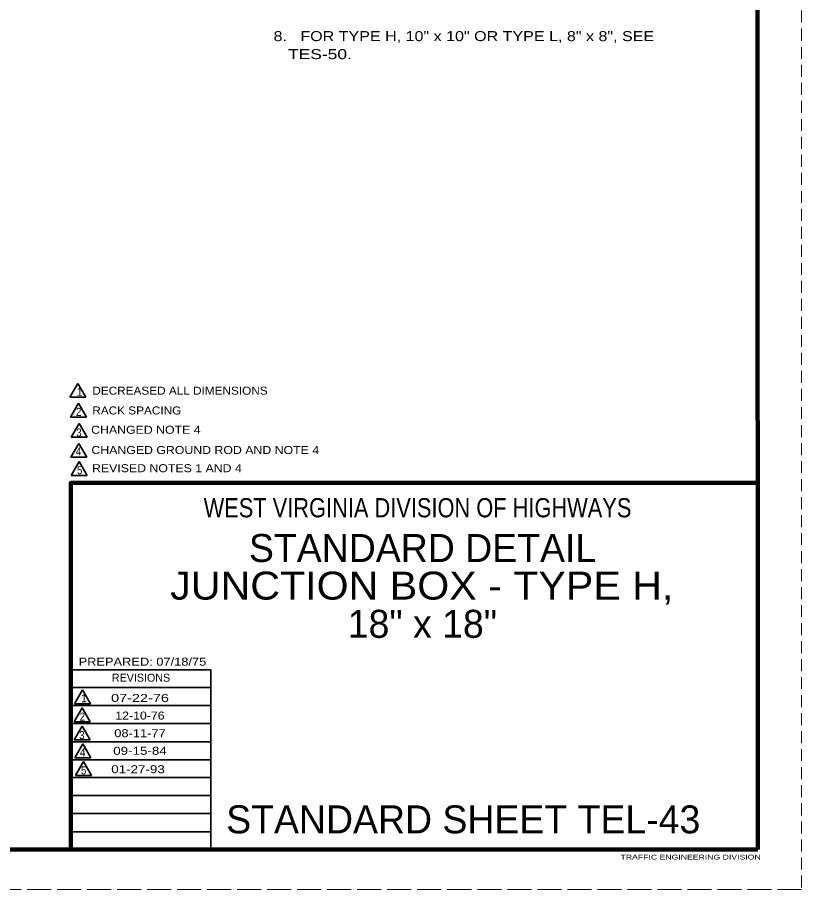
# Model space of a CAD drawing. Extents: x 788 to 1469, y -1 to 439.
# Drawn here: x 1272.6 to 1468.5, y -1 to 216.9 of the extents above; entities that cross this region are included whole.
import ezdxf
from ezdxf.enums import TextEntityAlignment as Align

# ---------------------------------------------------------------- set-up
doc = ezdxf.new("R2010")
doc.units = 0
doc.linetypes.add('LONG_DASHED', pattern=[7.5, 6, -1.5])
doc.linetypes.add('MEDIUM_DASHED', pattern=[4.5, 3, -1.5])
doc.layers.add('1', color=7, linetype='Continuous', lineweight=35)
doc.layers.add('61', color=7, linetype='Continuous', lineweight=35)

msp = doc.modelspace()

# ---------------------------------------------------------------- linework, layer by layer
at = {"layer": '1', "linetype": 'MEDIUM_DASHED', "lineweight": 13}
msp.add_line((1468.547, 439.076), (1468.527, -0.944), dxfattribs=at)
at = {"layer": '1'}
for p, q in [((1287.672, 125.464), (1285.672, 122)), ((1287.672, 125.464), (1289.672, 122)), ((1289.672, 122), (1285.672, 122)), ((1287.897, 120.518), (1285.897, 117.054)), ((1287.897, 120.518), (1289.897, 117.054)), ((1289.897, 117.054), (1285.897, 117.054)), ((1287.989, 115.479), (1285.989, 112.015)), ((1287.989, 115.479), (1289.989, 112.015)), ((1289.989, 112.015), (1285.989, 112.015)), ((1287.91, 110.492), (1285.91, 107.028)), ((1287.91, 110.492), (1289.91, 107.028)), ((1289.91, 107.028), (1285.91, 107.028)), ((1288.063, 105.955), (1286.063, 102.491)), ((1288.063, 105.955), (1290.063, 102.491)), ((1290.063, 102.491), (1286.063, 102.491)), ((1320.927, 49.476), (1285.947, 49.476)), ((1288.881, 48.884), (1286.881, 45.42)), ((1288.881, 48.884), (1290.881, 45.42)), ((1320.927, 44.976), (1285.947, 44.976)), ((1288.805, 44.425), (1286.805, 40.96)), ((1290.881, 45.42), (1286.881, 45.42)), ((1288.805, 44.425), (1290.805, 40.96)), ((1320.927, 40.476), (1285.947, 40.476)), ((1288.804, 39.889), (1286.804, 36.425)), ((1290.805, 40.96), (1286.805, 40.96)), ((1288.804, 39.889), (1290.804, 36.425)), ((1320.927, 35.956), (1285.947, 35.956)), ((1290.804, 36.425), (1286.804, 36.425)), ((1288.977, 35.43), (1286.977, 31.966)), ((1288.977, 35.43), (1290.977, 31.966)), ((1320.927, 31.476), (1285.947, 31.476)), ((1290.977, 31.966), (1286.977, 31.966)), ((1289.088, 31.031), (1287.088, 27.567)), ((1289.088, 31.031), (1291.088, 27.567)), ((1320.927, 26.996), (1285.947, 26.996)), ((1291.088, 27.567), (1287.088, 27.567)), ((1320.927, 22.496), (1285.947, 22.496)), ((1320.927, 17.996), (1285.947, 17.996)), ((1320.927, 13.476), (1285.947, 13.476))]:
    msp.add_line(p, q, dxfattribs=at)
at = {"layer": '1', "lineweight": 158}
msp.add_lwpolyline([(1285.927, 9.036), (1285.927, 100.616), (1457.587, 100.616)], dxfattribs=at)
at = {"layer": '1'}
msp.add_lwpolyline([(1320.927, 8.996), (1320.927, 53.956), (1285.947, 53.956)], dxfattribs=at)
at = {"layer": '61', "lineweight": 158}
for p, q in [((1457.567, 429.076), (1457.587, 9.036)), ((1457.587, 9.036), (818.527, 9.056))]:
    msp.add_line(p, q, dxfattribs=at)
at = {"layer": '61', "linetype": 'LONG_DASHED', "lineweight": 13}
msp.add_line((1468.527, -0.944), (788.467, -0.964), dxfattribs=at)

# ---------------------------------------------------------------- texts
at = {"layer": '1'}
for s, height, width, p in [('8.   FOR TYPE H, 10" x 10" OR TYPE L, 8" x 8", SEE', 2.5, 1.2, (1336.609, 210.962)), ('   TES-50.', 2.5, 1.3, (1336.609, 206.462)), ('DECREASED ALL DIMENSIONS', 2, 1.1, (1291.312, 122.651)), ('2', 2, 0.9, (1287.233, 117.364)), ('RACK SPACING', 2, 1.1, (1291.312, 117.709)), ('3', 2, 0.9, (1287.29, 112.192)), ('CHANGED NOTE 4', 2, 1.15, (1291.024, 112.881)), ('4', 2, 0.95, (1287.175, 107.48)), ('CHANGED GROUND ROD AND NOTE 4', 2, 1.15, (1291.082, 107.824)), ('5', 2, 0.9, (1287.483, 102.788)), ('REVISED NOTES 1 AND 4', 2, 1.15, (1291.236, 103.287)), ('PREPARED: 07/18/75', 1.998, 1.2, (1287.887, 54.956)), ('2', 2, 0.9, (1288.146, 41.222)), ('3', 2, 0.9, (1288.031, 36.605)), ('4', 2, 0.95, (1288.184, 32.293)), ('5', 2, 0.9, (1288.479, 27.82)), ('TRAFFIC ENGINEERING DIVISION', 1.2, 1.35, (1423.307, 6.536))]:
    msp.add_text(s, height=height, dxfattribs=dict(at, width=width)).set_placement(p)
for s, height, p in [('1', 2, (1287.405, 122.363)), ('REVISIONS', 1.998, (1296.207, 50.956)), ('1', 2, (1288.489, 45.839)), ('STANDARD SHEET TEL-43', 6.993, (1324.767, 13.076))]:
    msp.add_text(s, height=height, dxfattribs=at).set_placement(p)
for s, height, width, p in [('WEST VIRGINIA DIVISION OF HIGHWAYS', 4.795, 0.85, (1372.576, 92.016)), ('JUNCTION BOX - TYPE H,', 6.993, 1.1, (1373.646, 71.461)), ('07-22-76', 2, 1.35, (1303.227, 45.896)), ('12-10-76', 2, 1.15, (1303.207, 41.496)), ('08-11-77', 2, 1.2, (1303.227, 37.096)), ('09-15-84', 2, 1.25, (1303.227, 32.696)), ('01-27-93', 2, 1.25, (1302.737, 28.096))]:
    msp.add_text(s, height=height, dxfattribs=dict(at, width=width)).set_placement(p, align=Align.CENTER)
for s, p in [('STANDARD DETAIL', (1373.844, 80.856)), ('18" x 18"', (1373.798, 61.914))]:
    msp.add_text(s, height=6.993, dxfattribs=at).set_placement(p, align=Align.CENTER)

doc.saveas('drawing.dxf')
